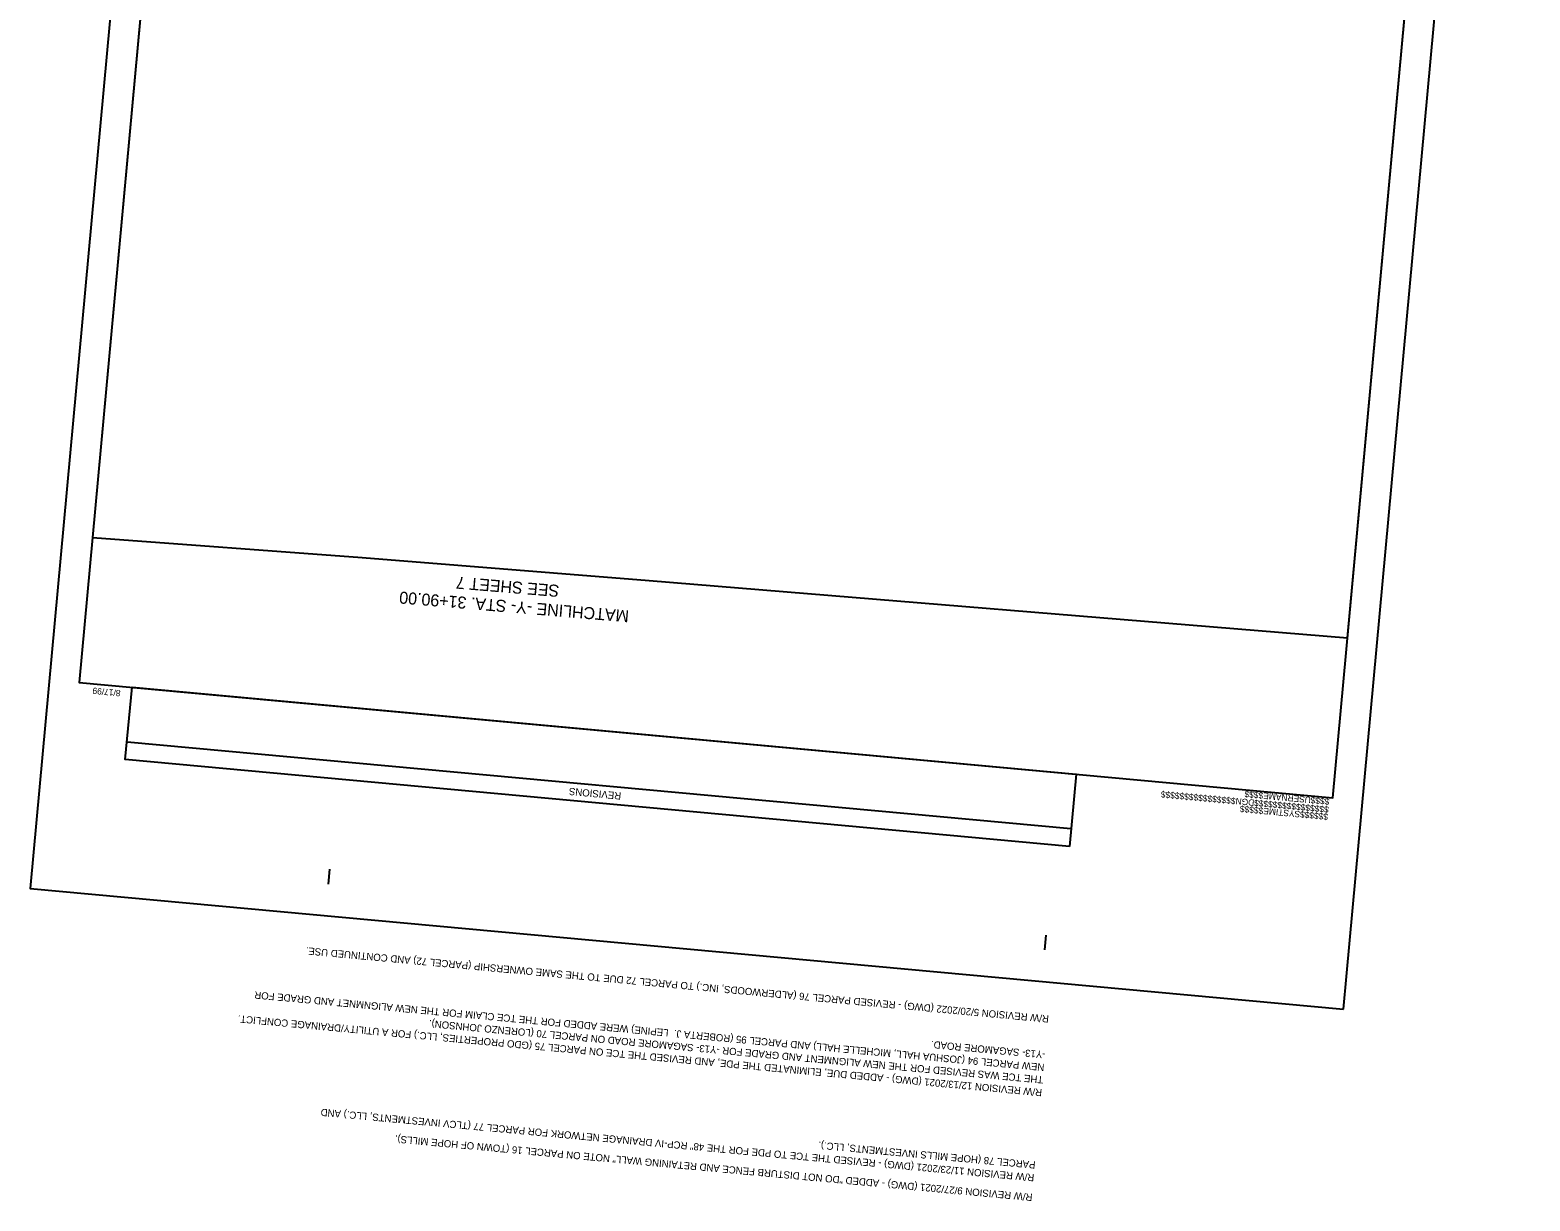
# Model space of a CAD drawing. Extents: x 2012234 to 2013485, y 445892 to 447846.
# Drawn here: x 2012234 to 2013485, y 445892 to 446869 of the extents above; entities that cross this region are included whole.
import ezdxf

# ---------------------------------------------------------------- set-up
doc = ezdxf.new("R2010")
doc.units = 0
for name, color, linetype in [('Matchline', 7, 'Continuous'), ('Matchline Text', 7, 'Continuous'), ('Old_Level_1', 7, 'Continuous'), ('Sheet Block Revision CELL', 7, 'Continuous'), ('Sheet Block System Information CELL', 7, 'Continuous'), ('Sheet Clip Boundary CELL', 7, 'Continuous'), ('Sheet Plan And Profile CELL', 7, 'Continuous'), ('Sheet Plot Border Outside CELL', 7, 'Continuous')]:
    doc.layers.add(name, color=color, linetype=linetype)

msp = doc.modelspace()

# ---------------------------------------------------------------- linework, layer by layer
at = {"layer": 'Matchline'}
msp.add_line((2012511.4, 446429.2), (2012750.7, 446410.1), dxfattribs=at)
at = {"layer": 'Sheet Block Revision CELL'}
msp.add_line((2013102.5, 446202.8), (2012315.2, 446275.2), dxfattribs=at)
msp.add_lwpolyline([(2013101.2, 446188.3), (2012313.8, 446260.7), (2012319.4, 446321), (2013106.7, 446248.6)], close=True, dxfattribs=at)
at = {"layer": 'Sheet Block System Information CELL'}
msp.add_line((2013320.8, 446228.9), (2013320.8, 446228.9), dxfattribs=at)
at = {"layer": 'Sheet Clip Boundary CELL'}
msp.add_lwpolyline([(2012286.3, 446445.8), (2012511.4, 446429.2), (2012750.7, 446410.1), (2013333, 446362.1), (2013458.1, 447722.6), (2012593.8, 447802.1), (2012575.5, 447602.9), (2012460.6, 447613.5), (2012442.3, 447414.3), (2012375.9, 447420.4)], close=True, dxfattribs=at)
at = {"layer": 'Sheet Plan And Profile CELL'}
for p, q in [((2013320.8, 446228.9), (2013320.8, 446228.9)), ((2013320.8, 446228.9), (2013320.8, 446228.9)), ((2013320.8, 446228.9), (2013320.8, 446228.9)), ((2013320.8, 446228.9), (2013320.8, 446228.9)), ((2013320.8, 446228.9), (2013320.8, 446228.9)), ((2012483.2, 446156.8), (2012484.3, 446169.3)), ((2013080.7, 446101.9), (2013081.8, 446114.3))]:
    msp.add_line(p, q, dxfattribs=at)
msp.add_lwpolyline([(2012412.6, 447818.8), (2012275.2, 446325.1), (2013320.8, 446228.9), (2013458.1, 447722.6)], close=True, dxfattribs=at)
at = {"layer": 'Sheet Plot Border Outside CELL'}
msp.add_lwpolyline([(2013329.7, 446052.4), (2013485.3, 447745.2), (2012389.9, 447846), (2012234.3, 446153.1)], close=True, dxfattribs=at)

# ---------------------------------------------------------------- texts
at = {"layer": 'Matchline Text'}
for s, p in [('SEE SHEET 7', (2012676, 446406.2)), ('MATCHLINE -Y- STA. 31+90.00', (2012734.2, 446385.1))]:
    msp.add_text(s, height=10, rotation=175.2749, dxfattribs=at).set_placement(p)
at = {"layer": 'Old_Level_1'}
for s, p in [('R/W REVISION 5/20/2022 (DWG) - REVISED PARCEL 76 (ALDERWOODS, INC.) TO PARCEL 72 DUE TO THE SAME OWNERSHIP (PARCEL 72) AND CONTINUED USE.  ', (2013084.3, 446047.2)), ('NEW PARCEL 94 (JOSHUA HALL, MICHELLE HALL) AND PARCEL 95 (ROBERTA J.  LEPINE) WERE ADDED FOR THE TCE CLAIM FOR THE NEW ALIGNMNET AND GRADE FOR ', (2013080.5, 446006.8)), ('R/W REVISION 12/13/2021 (DWG) - ADDED DUE, ELIMINATED THE PDE, AND REVISED THE TCE ON PARCEL 75 (GDO PROPERTIES, LLC.) FOR A UTILITY/DRAINAGE CONFLICT.  ', (2013078.6, 445985.8)), ('THE TCE WAS REVISED FOR THE NEW ALIGNMENT AND GRADE FOR -Y13- SAGAMORE ROAD ON PARCEL 70 (LORENZO JOHNSON).', (2013079.6, 445996.4)), ('-Y13- SAGAMORE ROAD.', (2013081.5, 446017.3)), ('R/W REVISION 11/23/2021 (DWG) - REVISED THE TCE TO PDE FOR THE 48" RCP-IV DRAINAGE NETWORK FOR PARCEL 77 (TLCV INVESTMENTS, LLC.) AND ', (2013072.1, 445914.8)), ('R/W REVISION 9/27/2021 (DWG) - ADDED "DO NOT DISTURB FENCE AND RETAINING WALL" NOTE ON PARCEL 16 (TOWN OF HOPE MILLS).', (2013070.6, 445898.4)), ('PARCEL 78 (HOPE MILLS INVESTMENTS, LLC.).', (2013073.1, 445925.4))]:
    msp.add_text(s, height=6, rotation=174.7467, dxfattribs=at).set_placement(p)
at = {"layer": 'Sheet Block Revision CELL'}
msp.add_text('REVISIONS', height=6, rotation=174.7467, dxfattribs=at).set_placement((2012727.6, 446233.2))
at = {"layer": 'Sheet Block System Information CELL'}
for s, p in [('$$$$$$$$$$$$$$$$DGN$$$$$$$$$$$$$$$$', (2013317.8, 446221.5)), ('$$$$USERNAME$$$$', (2013318.3, 446228.1)), ('$$$$$$SYSTIME$$$$$', (2013317.2, 446215.5))]:
    msp.add_text(s, height=5.25, rotation=174.7467, dxfattribs=at).set_placement(p)
at = {"layer": 'Sheet Plan And Profile CELL'}
msp.add_text('8/17/99', height=5.25, rotation=174.7467, dxfattribs=at).set_placement((2012310, 446318.6))

doc.saveas('drawing.dxf')
